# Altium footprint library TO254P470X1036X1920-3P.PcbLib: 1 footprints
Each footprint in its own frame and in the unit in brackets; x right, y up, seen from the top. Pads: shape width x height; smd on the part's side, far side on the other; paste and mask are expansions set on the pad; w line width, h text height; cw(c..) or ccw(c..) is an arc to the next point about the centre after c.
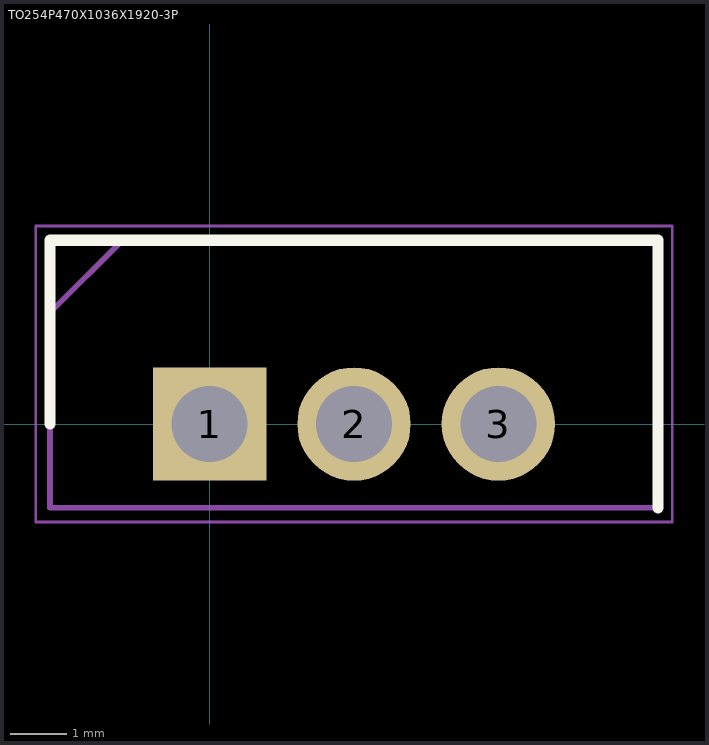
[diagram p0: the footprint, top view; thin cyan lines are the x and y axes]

## TO254P470X1036X1920-3P [mm]
pads (3):
  rect 1.995x1.995 / inner round 1.995 / far side rect 1.995x1.995 hole 1.33: 1(0,0)
  round 1.995 hole 1.33: 2(2.54,0) 3(5.08,0)
Top Overlay:
  lines w0.2: -2.805,0 -2.805,3.229 7.885,3.229 7.885,-1.47
Mechanical 15:
  lines w0.1: -2.805,1.959 -1.535,3.229 ; -2.805,-1.47 7.885,-1.47 7.885,3.229 -2.805,3.229 -2.805,-1.47
Mechanical 20:
  lines w0.05: -3.055,-1.72 8.135,-1.72 8.135,3.479 -3.055,3.479 -3.055,-1.72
